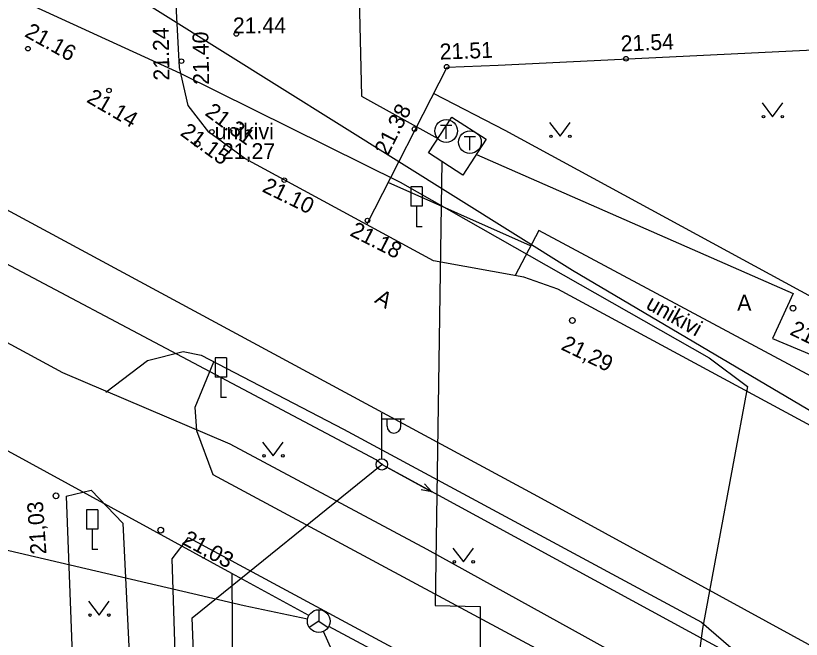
# Model space of a CAD drawing. Extents: x 714038 to 714279, y 6589845 to 6590041.
# Drawn here: x 714160.6 to 714195.16, y 6589933.15 to 6589960.57 of the extents above; entities that cross this region are included whole.
import ezdxf

# ---------------------------------------------------------------- set-up
doc = ezdxf.new("R2010")
doc.units = 0
for name, color, linetype in [('HALJASTUS', 7, 'Continuous'), ('HOONE', 7, 'Continuous'), ('KORGUS', 7, 'Continuous'), ('LIIKLUS', 7, 'Continuous'), ('MPKAABEL', 7, 'Continuous'), ('MPOHULIIN', 7, 'Continuous'), ('POST', 7, 'Continuous'), ('RAJATIS', 7, 'Continuous'), ('SIKAEV', 7, 'Continuous'), ('SITRASS', 7, 'Continuous'), ('SKTRASS', 7, 'Continuous'), ('TEE', 7, 'Continuous'), ('TKAEV', 7, 'Continuous'), ('TTRASS', 7, 'Continuous'), ('VTRASS', 7, 'Continuous')]:
    doc.layers.add(name, color=color, linetype=linetype)

msp = doc.modelspace()

# ---------------------------------------------------------------- linework, layer by layer
at = {"layer": 'HALJASTUS'}
for p, q in [((714193.437, 6589956.737), (714193.9, 6589956.13)), ((714193.9, 6589956.13), (714194.346, 6589956.737)), ((714184.087, 6589955.877), (714184.55, 6589955.27)), ((714184.55, 6589955.27), (714184.996, 6589955.877)), ((714171.462, 6589941.823), (714171.925, 6589941.217)), ((714171.925, 6589941.217), (714172.371, 6589941.823)), ((714179.836, 6589937.163), (714180.299, 6589936.556)), ((714180.299, 6589936.556), (714180.745, 6589937.163)), ((714163.805, 6589934.821), (714164.268, 6589934.215)), ((714164.268, 6589934.215), (714164.714, 6589934.821))]:
    msp.add_line(p, q, dxfattribs=at)
for centre in [(714193.499, 6589956.13), (714194.328, 6589956.13), (714184.149, 6589955.27), (714184.978, 6589955.27), (714171.524, 6589941.217), (714172.353, 6589941.217), (714179.898, 6589936.556), (714180.727, 6589936.556), (714163.867, 6589934.215), (714164.696, 6589934.215)]:
    msp.add_circle(centre, 0.055, dxfattribs=at)
at = {"layer": 'HOONE'}
msp.add_lwpolyline([(714037.81, 6590017.576), (714059.08, 6590006.51), (714072.38, 6589999.69), (714082.14, 6589994.37), (714104.85, 6589981.96), (714150.21, 6589957.43), (714183.55, 6589939.45), (714202.68, 6589928.99), (714214.04, 6589922.75), (714222.92, 6589918.06), (714237.47, 6589910.29), (714252.27, 6589902.23), (714256.602, 6589899.815), (714258.577, 6589898.715), (714261.69, 6589896.98)], dxfattribs=at)
at = {"layer": 'KORGUS'}
for centre, radius in [((714170.305, 6589959.768), 0.1), ((714161.135, 6589959.124), 0.1), ((714187.447, 6589958.681), 0.1), ((714167.89, 6589958.573), 0.1), ((714179.561, 6589958.328), 0.1), ((714164.704, 6589957.281), 0.1), ((714178.145, 6589955.587), 0.1), ((714169.228, 6589955.465), 0.1), ((714168.58, 6589954.94), 0.125), ((714172.415, 6589953.34), 0.1), ((714176.074, 6589951.57), 0.1), ((714194.8, 6589947.71), 0.125), ((714185.09, 6589947.17), 0.125), ((714162.37, 6589939.46), 0.125), ((714166.98, 6589937.95), 0.125)]:
    msp.add_circle(centre, radius, dxfattribs=at)
at = {"layer": 'LIIKLUS'}
for points in [[(714177.982, 6589953.044), (714177.982, 6589952.194)], [(714178.482, 6589953.044), (714177.982, 6589953.044)], [(714178.482, 6589953.044), (714178.482, 6589952.194)], [(714178.482, 6589952.194), (714177.982, 6589952.194)], [(714178.232, 6589952.194), (714178.232, 6589951.294)], [(714178.482, 6589951.294), (714178.232, 6589951.294)], [(714169.372, 6589945.533), (714169.372, 6589944.683)], [(714169.872, 6589945.533), (714169.372, 6589945.533)], [(714169.872, 6589945.533), (714169.872, 6589944.683)], [(714169.872, 6589944.683), (714169.372, 6589944.683)], [(714169.622, 6589944.683), (714169.622, 6589943.783)], [(714169.872, 6589943.783), (714169.622, 6589943.783)], [(714163.713, 6589938.845), (714163.713, 6589937.995)], [(714164.213, 6589938.845), (714163.713, 6589938.845)], [(714164.213, 6589938.845), (714164.213, 6589937.995)], [(714164.213, 6589937.995), (714163.713, 6589937.995)], [(714163.963, 6589937.995), (714163.963, 6589937.095)], [(714164.213, 6589937.095), (714163.963, 6589937.095)]]:
    msp.add_lwpolyline(points, dxfattribs=at)
at = {"layer": 'MPKAABEL'}
for points in [[(714123.717, 6589997.796), (714122.485, 6589997.244), (714122.51, 6589991.06), (714122.373, 6589988.225), (714122.093, 6589982.401), (714122.625, 6589980.577), (714131.807, 6589975.295), (714155.806, 6589963.558), (714167.836, 6589958.048), (714177.51, 6589953.25), (714191.113, 6589945.528), (714192.794, 6589944.261), (714190.81, 6589933.623), (714190.196, 6589929.064), (714190.863, 6589919.753), (714192.278, 6589911.176), (714192.96, 6589897.79), (714194.31, 6589864.41), (714194.86, 6589849.85), (714194.551, 6589845.18)], [(714176.708, 6589940.841), (714176.463, 6589941.047), (714151.383, 6589954.327)], [(714168.887, 6589920.442), (714168.368, 6589934.101), (714176.708, 6589940.841)], [(714205.454, 6589925.211), (714176.708, 6589940.841)]]:
    msp.add_lwpolyline(points, dxfattribs=at)
at = {"layer": 'MPOHULIIN'}
for p, q in [((714176.928, 6589940.721), (714178.901, 6589939.64)), ((714178.901, 6589939.64), (714178.578, 6589939.988)), ((714178.901, 6589939.64), (714178.434, 6589939.727))]:
    msp.add_line(p, q, dxfattribs=at)
at = {"layer": 'POST'}
for p, q in [((714176.708, 6589941.091), (714176.708, 6589943.091)), ((714176.708, 6589942.841), (714177.708, 6589942.841)), ((714176.935, 6589942.52), (714176.935, 6589942.841)), ((714177.548, 6589942.52), (714177.548, 6589942.841))]:
    msp.add_line(p, q, dxfattribs=at)
for radius in [0.25, 0.0234]:
    msp.add_circle((714176.708, 6589940.841), radius, dxfattribs=at)
msp.add_arc((714177.241, 6589942.52), 0.306, 180, 0, dxfattribs=at)
at = {"layer": 'RAJATIS'}
msp.add_lwpolyline([(714178.767, 6589954.541), (714179.79, 6589956.117), (714181.3, 6589955.137), (714180.277, 6589953.561)], close=True, dxfattribs=at)
at = {"layer": 'SIKAEV'}
for p, q in [((714173.931, 6589934.45), (714173.931, 6589933.95)), ((714173.931, 6589933.95), (714173.516, 6589933.675)), ((714173.931, 6589933.95), (714174.346, 6589933.675))]:
    msp.add_line(p, q, dxfattribs=at)
msp.add_circle((714173.931, 6589933.95), 0.5, dxfattribs=at)
at = {"layer": 'SITRASS'}
for points in [[(714173.493, 6589934.191), (714170.111, 6589936.05), (714128.857, 6589958.592)], [(714147.16, 6589938.495), (714160.301, 6589937.06), (714170.651, 6589934.64), (714173.442, 6589934.053)], [(714170.111, 6589936.05), (714170.217, 6589919.751), (714170.33, 6589894.92), (714173.196, 6589845.18)], [(714227.213, 6589905.211), (714223.017, 6589907.372), (714207.091, 6589915.92), (714188.911, 6589925.93), (714174.372, 6589933.714)], [(714180.413, 6589919.49), (714174.136, 6589933.494)]]:
    msp.add_lwpolyline(points, dxfattribs=at)
at = {"layer": 'SKTRASS'}
msp.add_lwpolyline([(714161.935, 6589963.885), (714185.098, 6589949.388), (714203.298, 6589938.638), (714203.3, 6589938.638)], dxfattribs=at)
at = {"layer": 'TEE'}
for points in [[(714195.768, 6589942.431), (714184.455, 6589948.554), (714182.951, 6589949.081), (714178.977, 6589949.797), (714170.686, 6589954.288), (714169.092, 6589955.445), (714168.184, 6589956.63), (714167.808, 6589958.298), (714167.098, 6589971.521), (714167.324, 6589972.468), (714168.034, 6589973.172), (714171.434, 6589975.354), (714171.239, 6589980.323), (714171.896, 6589980.348), (714171.817, 6589981.365), (714171.201, 6589981.347), (714171.023, 6589985.866)], [(714176.044, 6589951.385), (714179.585, 6589958.303), (714181.822, 6589958.396), (714214.375, 6589959.974)], [(714178.996, 6589957.153), (714182.127, 6589955.541)], [(714182.127, 6589955.541), (714203.579, 6589943.89), (714216.913, 6589936.58), (714217.539, 6589936.495), (714217.759, 6589936.392), (714218.3, 6589936.729)], [(714183.256, 6589950.45), (714176.993, 6589953.239)], [(714195.915, 6589942.281), (714196.868, 6589944.026), (714183.617, 6589951.131), (714182.568, 6589949.15)], [(714164.566, 6589944.019), (714166.398, 6589945.415), (714167.963, 6589945.809), (714168.756, 6589945.647), (714175.02, 6589942.389), (714190.78, 6589933.9), (714192.062, 6589932.786), (714192.489, 6589932.078), (714193.46, 6589928.012), (714192.441, 6589927.945), (714169.28, 6589940.376), (714168.562, 6589942.32), (714168.489, 6589943.358), (714169.312, 6589945.358)], [(714162.813, 6589939.444), (714163.911, 6589939.713), (714165.306, 6589938.253), (714166.184, 6589920.506), (714166.27, 6589917.366), (714165.473, 6589916.665), (714163.712, 6589916.586)], [(714162.813, 6589939.444), (714163.533, 6589920.503), (714163.668, 6589917.469), (714164.335, 6589904.221), (714165.868, 6589869.44), (714165.927, 6589867.283), (714166.738, 6589849.72), (714166.932, 6589845.18)], [(714193.799, 6589923.828), (714192.974, 6589923.166), (714177.25, 6589922.243), (714175.908, 6589921.844), (714168.108, 6589917.067), (714167.485, 6589936.695), (714168.201, 6589937.63)], [(714168.201, 6589937.63), (714193.799, 6589923.828)]]:
    msp.add_lwpolyline(points, dxfattribs=at)
at = {"layer": 'TKAEV'}
for p, q in [((714179.289, 6589955.754), (714179.789, 6589955.754)), ((714179.539, 6589955.154), (714179.539, 6589955.754)), ((714180.335, 6589955.262), (714180.835, 6589955.262)), ((714180.585, 6589954.662), (714180.585, 6589955.262))]:
    msp.add_line(p, q, dxfattribs=at)
for centre in [(714179.539, 6589955.504), (714180.585, 6589955.012)]:
    msp.add_circle(centre, 0.5, dxfattribs=at)
at = {"layer": 'TTRASS'}
for points in [[(714175.584, 6589966.934), (714175.81, 6589957.03), (714179.175, 6589955.169)], [(714180.868, 6589954.471), (714194.81, 6589948.35), (714193.9, 6589946.38), (714197.33, 6589944.94), (714198.25, 6589947.03), (714199.797, 6589946.458), (714205.14, 6589944.481), (714213.47, 6589941.4), (714220.708, 6589938.334), (714228.631, 6589935.107), (714230.913, 6589934.185)], [(714179.342, 6589954.168), (714179.05, 6589934.64), (714181.03, 6589934.59), (714181.03, 6589931.15), (714178.95, 6589931.17), (714178.54, 6589921.23), (714178.649, 6589919.425)]]:
    msp.add_lwpolyline(points, dxfattribs=at)
at = {"layer": 'VTRASS'}
msp.add_lwpolyline([(714219.771, 6589914.924), (714218.336, 6589915.691), (714204.329, 6589923.078), (714196.383, 6589927.305), (714185.655, 6589933.263), (714178.705, 6589937.104), (714170.033, 6589941.737), (714162.674, 6589944.874), (714154.781, 6589949.135), (714153.798, 6589949.498)], dxfattribs=at)

# ---------------------------------------------------------------- texts
at = {"layer": 'KORGUS'}
for s, p in [(' 21.44', (714169.892, 6589959.794)), ('21,27', (714169.671, 6589954.265))]:
    msp.add_text(s, height=0.7, dxfattribs=at).set_placement(p)
for s, rotation, p in [(' 21.16 ', 330.8396, (714160.722, 6589959.809)), (' 21.24', 90.9228, (714167.368, 6589957.465)), (' 21.40', 90.9228, (714169.113, 6589957.278)), (' 21.54', 2.3571, (714186.973, 6589958.987)), (' 21.51', 2.0514, (714179.005, 6589958.633)), (' 21.14 ', 329.8218, (714163.451, 6589956.928)), (' 21.31', 323.7911, (714168.675, 6589956.382)), (' 21.38', 63.0557, (714176.85, 6589954.142)), (' 21.15', 323.7911, (714167.584, 6589955.501)), (' 21.10 ', 333.9876, (714171.166, 6589952.972)), (' 21.18', 333.0972, (714175.031, 6589951.043)), ('21,21', 334.0139, (714194.621, 6589946.571)), ('21,29', 334.0139, (714184.551, 6589945.916)), ('21,03', 93.9434, (714161.952, 6589936.901)), ('21,03', 331.626, (714167.875, 6589937.363))]:
    msp.add_text(s, height=0.7, rotation=rotation, dxfattribs=at).set_placement(p)
at = {"layer": 'TEE'}
for s, p in [('unikivi', (714169.354, 6589955.134)), ('A', (714192.344, 6589947.607))]:
    msp.add_text(s, height=0.7, dxfattribs=at).set_placement(p)
for s, rotation, p in [('A', 329.4703, (714176.352, 6589947.986)), ('unikivi', 330.5024, (714188.281, 6589947.725))]:
    msp.add_text(s, height=0.7, rotation=rotation, dxfattribs=at).set_placement(p)

doc.saveas('drawing.dxf')
